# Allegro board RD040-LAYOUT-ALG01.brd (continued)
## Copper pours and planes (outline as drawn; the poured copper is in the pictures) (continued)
N20539 on TOP: 98.4,46.04 98.39,46 98.37,45.97 98.18,45.78 98.15,45.76 98.11,45.75 83.04,45.75 83,45.76 82.97,45.78 82.78,45.97 82.76,46 82.75,46.04 82.75,48.55 82.65,48.8 82.4,48.9 78.59,48.9 78.55,48.91 78.52,48.93 78.33,49.12 78.31,49.15 78.3,49.19 78.3,89.61 78.31,89.65 78.33,89.68 78.52,89.87 78.55,89.89 78.59,89.9 98.11,89.9 98.15,89.89 98.18,89.87 98.37,89.68 98.39,89.65 98.4,89.61 98.4,83.82 98.42,83.71 98.49,83.61 98.56,83.54 98.66,83.47 98.77,83.45 105.26,83.45 105.3,83.44 105.33,83.42 107.32,81.43 107.34,81.4 107.35,81.36 107.35,48.94 107.34,48.9 107.32,48.87 105.33,46.88 105.3,46.86 105.26,46.85 98.77,46.85 98.66,46.83 98.56,46.76 98.49,46.69 98.42,46.59 98.4,46.48 ; 23 cut-outs
N25173 on BOTTOM: 58.5,45.85 58.43,45.88 58.4,45.95 58.4,48.63 58.41,48.67 58.43,48.7 58.62,48.9 58.66,48.92 58.7,48.93 60.1,48.93 60.14,48.92 60.17,48.9 60.35,48.73 60.37,48.7 60.38,48.66 60.38,45.95 60.35,45.88 60.27,45.85
N25453 on BOTTOM: 55.72,45.33 55.68,45.33 55.65,45.35 55.45,45.55 55.43,45.58 55.42,45.62 55.42,46.91 55.43,46.95 55.45,46.98 55.6,47.12 55.63,47.14 55.67,47.15 57.1,47.15 57.17,47.12 57.2,47.05 57.2,45.52 57.19,45.48 57.17,45.45 57.08,45.35 57.05,45.33 57.01,45.33
N27553 on TOP: 50.9,66.53 50.88,66.64 50.81,66.74 50.76,66.79 50.67,66.85 50.55,66.88 45.12,66.88 45.08,66.88 45.05,66.9 44.88,67.07 44.86,67.1 44.85,67.14 44.85,70.41 44.86,70.45 44.88,70.48 45.25,70.85 45.28,70.87 45.32,70.88 50.67,70.88 54.77,74.97 54.8,74.99 54.84,75 60.36,75 60.4,74.99 60.43,74.97 60.62,74.78 60.64,74.75 60.65,74.71 60.65,71.72 60.64,71.68 60.62,71.65 58.65,69.67 58.54,69.51 58.5,69.32 58.5,66.93 58.49,66.89 58.47,66.86 57.51,65.89 57.35,65.67 57.3,65.4 57.3,58.99 57.29,58.95 57.27,58.92 57.15,58.8 57.12,58.78 57.08,58.77 52.62,58.77 52.58,58.78 52.55,58.8 50.71,60.64 50.62,60.7 50.5,60.73 47.95,60.73 47.95,63.77 50.55,63.77 50.67,63.8 50.76,63.86 50.81,63.91 50.88,64.01 50.9,64.12 ; 1 cut-out
N28004 on TOP: 70.55,41.45 70.48,41.48 70.45,41.55 70.45,46.46 70.46,46.5 70.48,46.53 72.52,48.57 72.55,48.59 72.59,48.6 82.35,48.6 82.42,48.57 82.45,48.5 82.45,42.7 82.42,42.63 82.35,42.6 76,42.6 75.23,41.83 75.2,41.81 75.16,41.8 73.25,41.8 72.93,41.48 72.9,41.46 72.86,41.45
N28004 on BOTTOM: 72.65,44.5 72.58,44.53 72.55,44.6 72.55,45.3 72.35,45.5 71.85,45.5 71.78,45.53 71.75,45.6 71.75,45.7 71.45,45.7 71.38,45.73 71.35,45.8 71.35,46.7 71.38,46.77 71.45,46.8 71.75,46.8 71.75,46.9 71.78,46.97 71.85,47 71.96,47 72,46.99 72.03,46.97 72.35,46.65 73.55,46.65 73.62,46.62 73.65,46.55 73.65,45.54 73.64,45.5 73.62,45.47 73.45,45.3 73.45,44.6 73.42,44.53 73.35,44.5
N78233 on TOP: 44.12,57.92 44.12,59.45 45.38,59.45 45.38,57.92
N78252 on TOP: 47.83,57.92 47.83,59.45 49.08,59.45 49.08,57.92

Small or netless copper shapes (teardrops, artwork), in the pictures only: 8 on TOP, 10 on BOTTOM, 1 on CONDUCTIVE3

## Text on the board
Ref Des/Silkscreen Top: P | Q | S | LGND | 0 GND | OUT+
